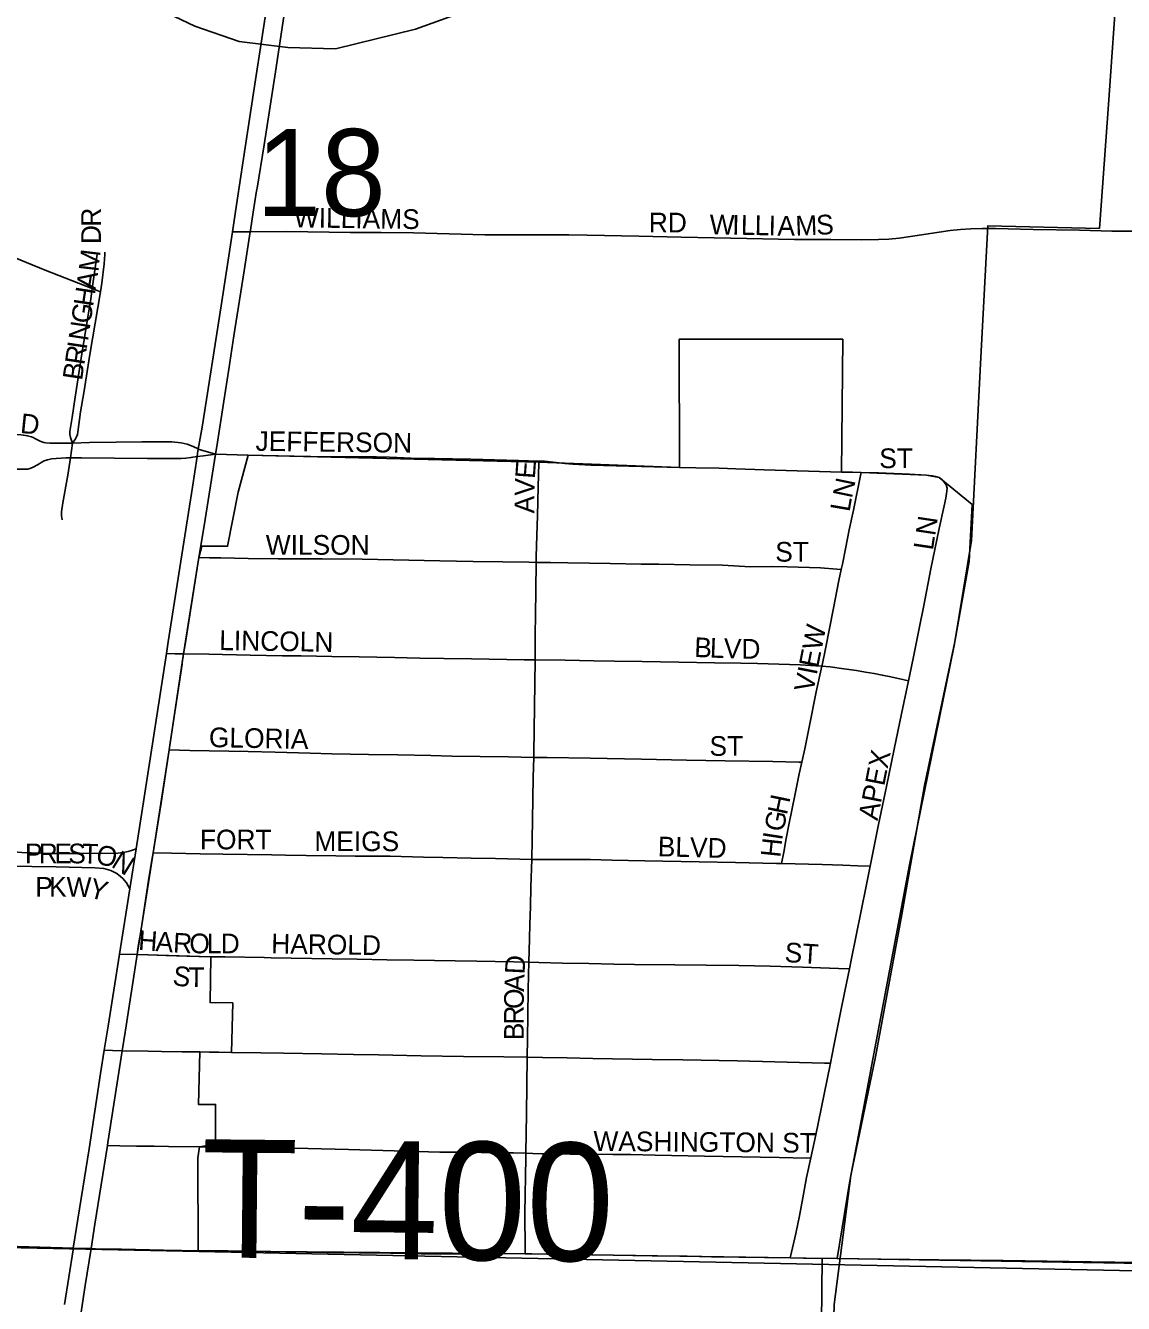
# Model space of a CAD drawing. Extents: x -5.6 to 34, y 0 to 22.
# Drawn here: x 3.932 to 5.047, y 16.786 to 18.084 of the extents above; entities that cross this region are included whole.
import ezdxf

# ---------------------------------------------------------------- set-up
doc = ezdxf.new("R2010")
doc.units = 0
for name, color, linetype in [('GM_X_City_Street', 7, 'Continuous'), ('GM_X_City_Street_Text', 7, 'Continuous'), ('GM_X_Corporation', 7, 'Continuous'), ('GM_X_County_Road', 7, 'Continuous'), ('GM_X_Minor_River', 7, 'Continuous'), ('GM_X_Section', 7, 'Continuous'), ('GM_X_Section_Text', 7, 'Continuous'), ('GM_X_State_Route', 7, 'Continuous'), ('GM_X_Township_Road', 7, 'Continuous'), ('GM_X_Township_Road_Text', 7, 'Continuous'), ('GM_X_Township_Subdivision', 7, 'Continuous'), ('GM_X_Township_Subdivision_Text', 7, 'Continuous')]:
    doc.layers.add(name, color=color, linetype=linetype)

msp = doc.modelspace()

# ---------------------------------------------------------------- linework, layer by layer
at = {"layer": 'GM_X_City_Street'}
for points in [[(3.7371, 17.9242), (3.7665, 17.9116), (3.8381, 17.8821), (3.9522, 17.8353), (4.0001, 17.8167)], [(4.1425, 17.8743), (4.1506, 17.8744), (4.1604, 17.8744)], [(4.1604, 17.8744), (4.1978, 17.8745), (4.2621, 17.8736), (4.2936, 17.8735), (4.3264, 17.8731), (4.3986, 17.8714), (4.4314, 17.8713), (4.4616, 17.8712), (4.4839, 17.8712), (4.5027, 17.8709), (4.5552, 17.8698), (4.5981, 17.869)], [(4.5981, 17.869), (4.6486, 17.8679), (4.7134, 17.8666), (4.7502, 17.8665), (4.7816, 17.8662), (4.7986, 17.8664), (4.8091, 17.8669), (4.8194, 17.8679), (4.8311, 17.8694), (4.8713, 17.8756), (4.8818, 17.8768), (4.8924, 17.8774), (4.9043, 17.8777), (4.9175, 17.8777), (4.9556, 17.8767), (5.0028, 17.8759), (5.0356, 17.8751), (5.0658, 17.875), (5.0814, 17.8746)], [(4.0001, 17.8167), (4.0049, 17.8515)], [(4.0084, 17.8135), (4.0098, 17.8223), (4.0122, 17.8419), (4.0128, 17.8511), (4.0128, 17.8537)], [(3.9801, 17.6598), (3.9779, 17.6655), (3.9774, 17.6686), (3.9773, 17.6716), (3.9795, 17.6857), (3.9827, 17.7064), (3.9895, 17.7505), (3.9986, 17.8061), (4.0001, 17.8167)], [(3.9801, 17.6598), (3.983, 17.664), (3.9841, 17.666), (3.9849, 17.6685), (3.9855, 17.6707), (3.988, 17.6913), (3.9916, 17.7107), (3.9976, 17.7497), (4.0084, 17.8135)], [(4.0001, 17.8167), (4.0033, 17.8155), (4.0084, 17.8135)], [(3.8748, 17.6684), (3.875, 17.6684), (3.9208, 17.6683), (3.9275, 17.668), (3.93, 17.6679), (3.9321, 17.6675), (3.9343, 17.6671), (3.9382, 17.6661), (3.9402, 17.6654), (3.9423, 17.6642), (3.945, 17.6627), (3.9471, 17.6617), (3.9489, 17.6609), (3.9508, 17.6604), (3.953, 17.66), (3.957, 17.6597), (3.9591, 17.6597), (3.9623, 17.6597), (3.9717, 17.6597), (3.9801, 17.6598)], [(3.9781, 17.6446), (3.9801, 17.6598)], [(3.9801, 17.6598), (3.9972, 17.6603), (4.0242, 17.6605), (4.0503, 17.6609), (4.0808, 17.661), (4.0904, 17.6599), (4.0964, 17.6586), (4.1009, 17.6569), (4.1063, 17.6544), (4.1077, 17.6535)], [(4.1077, 17.6535), (4.1252, 17.6484)], [(3.8695, 17.6341), (3.909, 17.6334), (3.9324, 17.6331), (3.9347, 17.6334), (3.9377, 17.6342), (3.9402, 17.6353), (3.9446, 17.6378), (3.9488, 17.6403), (3.9513, 17.6417), (3.9545, 17.6428), (3.9586, 17.6437), (3.9732, 17.6446), (3.9781, 17.6446)], [(3.9696, 17.5817), (3.9689, 17.5858), (3.9689, 17.5898), (3.9702, 17.599), (3.9752, 17.6272), (3.9781, 17.6446)], [(3.9781, 17.6446), (3.989, 17.6447), (4.056, 17.6441), (4.0755, 17.6439), (4.0902, 17.6441), (4.0951, 17.6444), (4.1002, 17.645), (4.1066, 17.6462)], [(4.1066, 17.6462), (4.113, 17.6469), (4.1252, 17.6484)], [(4.7607, 17.5314), (4.7619, 17.5369), (4.7652, 17.5523), (4.7689, 17.5716), (4.773, 17.5916), (4.7804, 17.6268), (4.781, 17.6299)], [(4.7411, 17.4331), (4.7413, 17.434), (4.7446, 17.4508), (4.7527, 17.492), (4.7582, 17.5203), (4.7607, 17.5314)], [(4.7206, 17.3356), (4.7236, 17.3493), (4.728, 17.3712), (4.7354, 17.4071), (4.7411, 17.4331)], [(4.7001, 17.2326), (4.7023, 17.2443), (4.7048, 17.258), (4.7077, 17.2736), (4.7135, 17.3018), (4.718, 17.3237), (4.7206, 17.3356)], [(3.9067, 17.2462), (3.9168, 17.2448), (3.9285, 17.2438), (3.9573, 17.2429), (3.9888, 17.2429), (4.026, 17.2431), (4.0315, 17.2438), (4.0365, 17.2449), (4.0409, 17.2464), (4.0446, 17.2476)], [(3.9044, 17.2302), (3.9135, 17.23), (3.9634, 17.2292), (4.0028, 17.2284), (4.0119, 17.2275), (4.0188, 17.2257), (4.025, 17.2225), (4.0288, 17.2194), (4.0311, 17.2174), (4.0347, 17.2131), (4.0381, 17.2069)], [(4.0277, 17.1408), (4.0455, 17.1403)], [(4.0455, 17.1403), (4.0567, 17.1399), (4.0747, 17.1393), (4.0962, 17.1386), (4.1204, 17.1378)], [(4.0121, 17.043), (4.0206, 17.0428), (4.0304, 17.0426)], [(4.0304, 17.0426), (4.0568, 17.042), (4.0705, 17.0419), (4.0912, 17.0416), (4.1092, 17.0414)], [(4.0154, 16.9463), (4.0282, 16.9461), (4.0449, 16.9458), (4.0629, 16.9455), (4.0774, 16.9453), (4.109, 16.9448)], [(3.6475, 16.8499), (3.6775, 16.849), (3.7428, 16.8476), (3.7952, 16.8468), (3.8507, 16.8457), (3.9128, 16.8441), (3.9808, 16.8421)], [(3.9808, 16.8421), (3.9989, 16.8416)], [(3.9989, 16.8416), (4.0032, 16.8415), (4.0299, 16.841), (4.0725, 16.8401), (4.0908, 16.8398), (4.1075, 16.8394)]]:
    msp.add_lwpolyline(points, dxfattribs=at)
at = {"layer": 'GM_X_Corporation'}
msp.add_lwpolyline([(4.7302, 15.7581), (4.7414, 16.8317), (4.7089, 16.8321), (4.4397, 16.8364), (4.1075, 16.8394), (4.1074, 16.9339), (4.109, 16.9448), (4.1253, 16.9476), (4.1253, 16.988), (4.1079, 16.988), (4.1092, 17.0414), (4.1415, 17.0407), (4.1428, 17.0912), (4.1197, 17.0914), (4.1204, 17.1378), (4.0455, 17.1403), (4.0619, 17.2437), (4.078, 17.3481), (4.0928, 17.4457), (4.1084, 17.5434), (4.1112, 17.555), (4.1375, 17.555), (4.1483, 17.6098), (4.1583, 17.6476), (4.4536, 17.6403), (4.5965, 17.6348), (4.5962, 17.7651), (4.7622, 17.7651), (4.7609, 17.6303), (4.781, 17.6299), (4.8472, 17.6271), (4.8602, 17.6247), (4.8937, 17.5973), (4.8907, 17.5394), (4.8755, 17.454), (4.8299, 17.2315), (4.769, 16.9084), (4.7565, 16.8316), (5.1314, 16.8255)], dxfattribs=at)
at = {"layer": 'GM_X_County_Road'}
for points in [[(4.1075, 16.8394), (4.1379, 16.8395), (4.1757, 16.8386), (4.2385, 16.8377), (4.3032, 16.8368), (4.3492, 16.8361), (4.4123, 16.8365), (4.4397, 16.8364)], [(4.4397, 16.8364), (4.4465, 16.8364), (4.5292, 16.8349), (4.5687, 16.8344), (4.6041, 16.8338), (4.6291, 16.8334), (4.6567, 16.8328), (4.7089, 16.8321)], [(4.7089, 16.8321), (4.7224, 16.832), (4.7565, 16.8316)], [(4.7565, 16.8316), (4.8009, 16.831), (4.8599, 16.8303), (4.9253, 16.8295), (5.0146, 16.8282), (5.0868, 16.8271), (5.1321, 16.8265)]]:
    msp.add_lwpolyline(points, dxfattribs=at)
at = {"layer": 'GM_X_Minor_River'}
for points in [[(5.0409, 18.1292), (5.0324, 18.0083), (5.0229, 17.8778), (4.9096, 17.8805), (4.9022, 17.7403), (4.893, 17.5609), (4.8761, 17.4578), (4.8454, 17.3118), (4.8223, 17.1808), (4.7956, 17.0363), (4.7703, 16.9158), (4.7536, 16.7847), (4.7464, 16.5218), (4.7413, 16.3446), (4.7361, 16.0969), (4.7291, 15.8428), (4.723, 15.5919), (4.717, 15.3426), (4.7103, 15.0997), (4.7043, 14.852)], [(4.0481, 18.1101), (4.1041, 18.0831), (4.1492, 18.0675), (4.1986, 18.0615), (4.2472, 18.0603), (4.3284, 18.08), (4.4129, 18.1108)]]:
    msp.add_lwpolyline(points, dxfattribs=at)
at = {"layer": 'GM_X_Section'}
for points in [[(3.1889, 18.9888), (5.3166, 18.9352), (5.2895, 16.8144), (3.1401, 16.8587)], [(3.1401, 16.8587), (5.2895, 16.8144), (5.2575, 14.6921), (3.0791, 14.7168)]]:
    msp.add_lwpolyline(points, close=True, dxfattribs=at)
at = {"layer": 'GM_X_State_Route'}
for points in [[(4.167, 17.916), (4.1675, 17.9188), (4.1745, 17.9628), (4.186, 18.0367), (4.2104, 18.199), (4.2115, 18.2069), (4.2215, 18.2783), (4.2284, 18.3225)], [(3.9719, 16.7847), (3.9806, 16.8404), (3.9808, 16.8421), (3.9969, 16.9429), (4.0084, 17.0195), (4.0121, 17.043), (4.0161, 17.0674), (4.0277, 17.1408), (4.0381, 17.2069), (4.0446, 17.2476), (4.0528, 17.2996), (4.0753, 17.4459), (4.0771, 17.4579), (4.0889, 17.5332), (4.1018, 17.6149), (4.1066, 17.6462), (4.1071, 17.6495), (4.1077, 17.6535), (4.1116, 17.6758), (4.1309, 17.799), (4.1425, 17.8743), (4.1467, 17.9016), (4.1553, 17.96), (4.1644, 18.0197), (4.1814, 18.13)], [(4.1252, 17.6484), (4.1265, 17.6561), (4.1337, 17.7024), (4.1386, 17.7348), (4.1439, 17.7685), (4.1542, 17.8346), (4.1604, 17.8744), (4.1607, 17.876), (4.1636, 17.8942), (4.167, 17.916)], [(4.0915, 17.4369), (4.0925, 17.4435), (4.0928, 17.4457), (4.0943, 17.4551), (4.1084, 17.5434), (4.1136, 17.5756), (4.1252, 17.6484)], [(4.0791, 17.3554), (4.0838, 17.3864), (4.0912, 17.4351), (4.0915, 17.4369)], [(4.0618, 17.2437), (4.0699, 17.2943), (4.078, 17.3481), (4.0791, 17.3554)], [(4.0455, 17.1403), (4.0468, 17.1483), (4.0493, 17.1635), (4.0576, 17.2179), (4.0613, 17.2399), (4.0618, 17.2437)], [(4.0334, 17.0613), (4.0337, 17.0635), (4.0455, 17.1403)], [(3.9989, 16.8416), (4.0028, 16.8663), (4.0154, 16.9463), (4.0159, 16.9493), (4.0304, 17.0426), (4.0334, 17.0613)], [(3.993, 16.8041), (3.9989, 16.8416)], [(3.9661, 16.6372), (3.9775, 16.7095), (3.9891, 16.7795), (3.993, 16.8041)]]:
    msp.add_lwpolyline(points, dxfattribs=at)
at = {"layer": 'GM_X_Township_Road'}
for points in [[(4.1092, 17.0414), (4.1191, 17.0412), (4.1287, 17.041), (4.1415, 17.0407)], [(4.1415, 17.0407), (4.1713, 17.0406), (4.1942, 17.0401), (4.2331, 17.0394), (4.2652, 17.0388), (4.2908, 17.0383), (4.3342, 17.0373), (4.3771, 17.0368), (4.4179, 17.0363), (4.4419, 17.036)], [(4.4419, 17.036), (4.4574, 17.0357), (4.4823, 17.0353), (4.5084, 17.0348), (4.5687, 17.0337), (4.5997, 17.0332), (4.6553, 17.0322), (4.7438, 17.03), (4.7497, 17.0299)]]:
    msp.add_lwpolyline(points, dxfattribs=at)
at = {"layer": 'GM_X_Township_Subdivision'}
for points in [[(4.1252, 17.6484), (4.1583, 17.6476), (4.1888, 17.6469), (4.2217, 17.6461), (4.2585, 17.6457), (4.2887, 17.6456), (4.3018, 17.6454), (4.3241, 17.6445), (4.3478, 17.644), (4.3846, 17.6433), (4.4331, 17.6422), (4.4536, 17.6414)], [(4.4509, 17.5386), (4.451, 17.5446), (4.4515, 17.5657), (4.4521, 17.5858), (4.4529, 17.6152), (4.4535, 17.6392), (4.4536, 17.6414)], [(4.4536, 17.6414), (4.4593, 17.6412), (4.4801, 17.6389), (4.488, 17.6382), (4.5064, 17.6374), (4.5577, 17.636), (4.5965, 17.6348)], [(4.5965, 17.6348), (4.6131, 17.6346), (4.6367, 17.6343), (4.6537, 17.6335), (4.6825, 17.6327), (4.7609, 17.6303)], [(4.7609, 17.6303), (4.772, 17.6301), (4.781, 17.6299)], [(4.781, 17.6299), (4.7986, 17.6295), (4.8302, 17.628), (4.8472, 17.6271), (4.8532, 17.6266), (4.8565, 17.6259), (4.8602, 17.6247), (4.8628, 17.6229), (4.8647, 17.6212), (4.8674, 17.6172)], [(4.829, 17.4183), (4.8337, 17.4411), (4.84, 17.4714), (4.8446, 17.4946), (4.8516, 17.532), (4.8603, 17.573), (4.8651, 17.5961), (4.8668, 17.6039), (4.868, 17.611), (4.8684, 17.6141), (4.8674, 17.6172)], [(4.1084, 17.5434), (4.1192, 17.5432), (4.1305, 17.5431), (4.1585, 17.5426), (4.189, 17.5422), (4.2336, 17.5422), (4.2743, 17.5418), (4.3531, 17.5402), (4.387, 17.5396), (4.4169, 17.5391), (4.4433, 17.5387), (4.4509, 17.5386)], [(4.4497, 17.4395), (4.4497, 17.4437), (4.45, 17.4653), (4.4502, 17.4849), (4.4505, 17.5104), (4.4509, 17.5386)], [(4.4509, 17.5386), (4.4655, 17.5384), (4.4829, 17.5381), (4.5051, 17.5377), (4.5259, 17.5374), (4.5574, 17.5369), (4.5755, 17.5366), (4.6068, 17.536), (4.64, 17.5356), (4.6685, 17.5341), (4.6906, 17.5343), (4.7059, 17.5341), (4.7396, 17.5331), (4.7563, 17.5317), (4.7607, 17.5314)], [(4.0753, 17.4459), (4.0843, 17.4458), (4.0928, 17.4457)], [(4.0928, 17.4457), (4.1185, 17.4453), (4.1605, 17.4444), (4.1934, 17.4438), (4.2121, 17.4435), (4.2432, 17.443), (4.271, 17.4425), (4.3071, 17.4418), (4.3329, 17.4413), (4.3571, 17.4409), (4.3853, 17.4405), (4.4211, 17.44), (4.4388, 17.4397), (4.4497, 17.4395)], [(4.4484, 17.3405), (4.4484, 17.3443), (4.4497, 17.4395)], [(4.4497, 17.4395), (4.4805, 17.4391), (4.5096, 17.4386), (4.5305, 17.4383), (4.5587, 17.4378), (4.5957, 17.4372), (4.632, 17.4366), (4.6587, 17.4362), (4.6758, 17.4358), (4.7191, 17.4346), (4.7348, 17.4336), (4.7411, 17.4331)], [(4.7411, 17.4331), (4.7493, 17.4324), (4.7633, 17.4306), (4.7763, 17.4286), (4.7852, 17.4271), (4.7941, 17.4256), (4.8023, 17.4241), (4.811, 17.4222), (4.8247, 17.4192), (4.829, 17.4183)], [(4.79, 17.2299), (4.7911, 17.235), (4.7986, 17.2723), (4.8066, 17.3109), (4.8145, 17.3487), (4.822, 17.3847), (4.829, 17.4183)], [(4.078, 17.3481), (4.0992, 17.3476), (4.1583, 17.3464), (4.1858, 17.3457), (4.2212, 17.3447), (4.2432, 17.3442), (4.2807, 17.3435), (4.3105, 17.343), (4.3438, 17.3423), (4.3653, 17.3419), (4.4229, 17.3409), (4.4484, 17.3405)], [(4.4464, 17.2369), (4.4468, 17.2571), (4.4472, 17.2772), (4.4476, 17.2984), (4.448, 17.3203), (4.4484, 17.3405)], [(4.4484, 17.3405), (4.4622, 17.3403), (4.5056, 17.3396), (4.558, 17.3386), (4.6034, 17.3378), (4.6427, 17.3371), (4.6912, 17.3362), (4.7178, 17.3357), (4.7206, 17.3356)], [(4.0618, 17.2437), (4.0807, 17.2433), (4.1096, 17.2426), (4.1325, 17.2423), (4.1825, 17.2416)], [(4.1825, 17.2416), (4.1963, 17.2413), (4.2173, 17.2409), (4.2475, 17.2406), (4.2672, 17.2403), (4.3027, 17.2401), (4.3365, 17.2393), (4.3561, 17.2389), (4.385, 17.2383), (4.4097, 17.2377), (4.4464, 17.2369)], [(4.4435, 17.1324), (4.4442, 17.1563), (4.4446, 17.1712), (4.4451, 17.189), (4.4456, 17.2091), (4.4464, 17.2369)], [(4.4464, 17.2369), (4.465, 17.2368), (4.5061, 17.2367), (4.5278, 17.2362), (4.5611, 17.2355), (4.6163, 17.2344), (4.6534, 17.2336), (4.6951, 17.2327), (4.7001, 17.2326)], [(4.7001, 17.2326), (4.7415, 17.2316), (4.7622, 17.231), (4.7776, 17.2305), (4.79, 17.2299)], [(4.769, 17.1257), (4.7709, 17.1347), (4.7809, 17.1846), (4.786, 17.2096), (4.79, 17.2299)], [(4.1204, 17.1378), (4.1351, 17.1379), (4.1745, 17.1372), (4.1816, 17.137)], [(4.1816, 17.137), (4.202, 17.1366), (4.2436, 17.1359), (4.269, 17.1354), (4.2991, 17.135), (4.3267, 17.1346), (4.3687, 17.1338), (4.3906, 17.1334), (4.4094, 17.1331), (4.4282, 17.1327), (4.4435, 17.1324)], [(4.4419, 17.036), (4.4421, 17.0545), (4.4424, 17.0791), (4.4429, 17.1042), (4.4432, 17.1198), (4.4435, 17.1324)], [(4.4435, 17.1324), (4.4537, 17.1321), (4.4777, 17.1316), (4.5045, 17.131), (4.5299, 17.1305), (4.5507, 17.1303), (4.5918, 17.1299), (4.6235, 17.1296), (4.6568, 17.1292), (4.6885, 17.1284), (4.7214, 17.1275), (4.7578, 17.1261), (4.769, 17.1257)], [(4.7497, 17.0299), (4.7531, 17.0475), (4.76, 17.0814), (4.7645, 17.1031), (4.769, 17.1257)], [(4.4403, 16.9384), (4.4412, 16.9786), (4.4419, 17.036)], [(4.7298, 16.9337), (4.7348, 16.9573), (4.7435, 16.9983), (4.7497, 17.0299)], [(4.109, 16.9448), (4.143, 16.9446), (4.1666, 16.9445), (4.1878, 16.944), (4.2193, 16.9434), (4.2602, 16.9422), (4.3529, 16.9395), (4.3792, 16.9394), (4.4107, 16.9389), (4.4278, 16.9387), (4.4403, 16.9384)], [(4.4397, 16.8364), (4.4396, 16.8408), (4.4394, 16.8775), (4.4403, 16.9339), (4.4403, 16.9384)], [(4.4403, 16.9384), (4.4474, 16.9382), (4.4565, 16.938), (4.4696, 16.9378), (4.4853, 16.9376), (4.5076, 16.9374), (4.5286, 16.9373), (4.547, 16.9371), (4.5716, 16.9366), (4.6219, 16.9356), (4.6597, 16.9348), (4.6977, 16.934), (4.7256, 16.9336), (4.7298, 16.9337)], [(4.7089, 16.8321), (4.7093, 16.8337), (4.7146, 16.857), (4.7182, 16.875), (4.7216, 16.8931), (4.7255, 16.9137), (4.7298, 16.9337)]]:
    msp.add_lwpolyline(points, dxfattribs=at)

# ---------------------------------------------------------------- texts
at = {"layer": 'GM_X_City_Street_Text'}
for s, rotation, p in [('WILLIAMS', 359.1714, (4.2047, 17.8789)), ('R', 89.994, (4.0089, 17.8795)), ('RD', 0, (4.5653, 17.8737)), ('W', 358.8566, (4.6269, 17.8719)), ('I', 358.8562, (4.6498, 17.8715)), ('L', 358.8511, (4.6586, 17.8713)), ('L', 358.8511, (4.6727, 17.871)), ('I', 358.8562, (4.6868, 17.8707)), ('A', 359.4636, (4.6958, 17.8705)), ('M', 2.2737, (4.7145, 17.8704)), ('S', 2.7165, (4.7357, 17.8712)), ('D', 89.8462, (4.0088, 17.8618)), ('M', 83.3447, (4.0061, 17.8331)), ('A', 81.4772, (4.0034, 17.815)), ('H', 81.4433, (4.0008, 17.7976)), ('G', 81.4772, (3.9982, 17.7802)), ('N', 81.4433, (3.9956, 17.7627)), ('R', 81.482, (3.9919, 17.7384)), ('I', 81.4433, (3.9943, 17.754)), ('B', 81.444, (3.9896, 17.7227)), ('D', 354.1546, (3.9263, 17.6701)), ('N', 78.2228, (4.7715, 17.6029)), ('L', 80.2278, (4.7691, 17.5892)), ('VIEW', 78.9312, (4.7323, 17.4059)), ('H', 78.2442, (4.7054, 17.2813)), ('G', 78.4715, (4.7019, 17.264)), ('I', 81.091, (4.7006, 17.2556)), ('P', 359.8634, (3.9317, 17.233)), ('R', 359.8632, (3.9457, 17.233)), ('E', 359.8634, (3.9616, 17.233)), ('S', 359.8634, (3.9757, 17.2329)), ('T', 358.6341, (3.9896, 17.2329)), ('O', 348.5143, (4.0028, 17.2327)), ('H', 84.0001, (4.6988, 17.2383)), ('N', 328.129, (4.0183, 17.2299)), ('P', 0, (3.9422, 17.199)), ('K', 359.9563, (3.9563, 17.199)), ('W', 359.2603, (3.9738, 17.199)), ('Y', 344.8292, (3.9954, 17.1989)), ('H', 355.9751, (4.0463, 17.145)), ('A', 355.9533, (4.0639, 17.1438)), ('R', 356.9386, (4.0818, 17.1425)), ('O', 359.5536, (4.0986, 17.1416)), ('L', 359.9956, (4.1164, 17.1415)), ('D', 359.9929, (4.1305, 17.1415)), ('S', 352.1056, (4.0809, 17.1094)), ('T', 359.3679, (4.0976, 17.1073))]:
    msp.add_text(s, height=0.02, rotation=rotation, dxfattribs=at).set_placement(p)
at = {"layer": 'GM_X_Section_Text'}
msp.add_text('18', height=0.0884, rotation=0, dxfattribs=at).set_placement((4.1666, 17.8903))
at = {"layer": 'GM_X_Township_Road_Text'}
msp.add_text('T-400', height=0.12, rotation=359.4401, dxfattribs=at).set_placement((4.1103, 16.8327))
at = {"layer": 'GM_X_Township_Subdivision_Text'}
for s, rotation, p in [('JEFFERSON', 359.2458, (4.1658, 17.6519)), ('ST', 0, (4.7993, 17.6343)), ('E', 86.0351, (4.4495, 17.6231)), ('V', 88.0326, (4.4489, 17.6057)), ('A', 89.9126, (4.4489, 17.5883)), ('LN', 81.473, (4.8538, 17.5502)), ('WILSON', 0, (4.1763, 17.5463)), ('ST', 0, (4.6937, 17.5393)), ('LINCOLN', 359.0748, (4.1289, 17.4495)), ('B', 357.887, (4.6112, 17.4425)), ('L', 357.8961, (4.627, 17.4419)), ('V', 358.2046, (4.6412, 17.4414)), ('D', 359.6841, (4.6593, 17.4408)), ('GLORIA', 358.8961, (4.1184, 17.351)), ('ST', 0, (4.6269, 17.3421)), ('APEX', 78.9963, (4.7975, 17.2757)), ('FORT', 0, (4.1094, 17.2471)), ('MEIGS', 0, (4.2256, 17.2453)), ('BLVD', 358.4933, (4.5742, 17.2401)), ('HAROLD', 359.0441, (4.1817, 17.1415)), ('ST', 356.4254, (4.7028, 17.1327)), ('D', 87.1791, (4.4391, 17.1199)), ('A', 87.7924, (4.4384, 17.1023)), ('O', 89.6939, (4.4383, 17.0849)), ('R', 89.9514, (4.4383, 17.0691)), ('B', 89.9757, (4.4383, 17.0533)), ('WASHINGTON ST', 359.4999, (4.509, 16.9409))]:
    msp.add_text(s, height=0.02, rotation=rotation, dxfattribs=at).set_placement(p)

doc.saveas('drawing.dxf')
